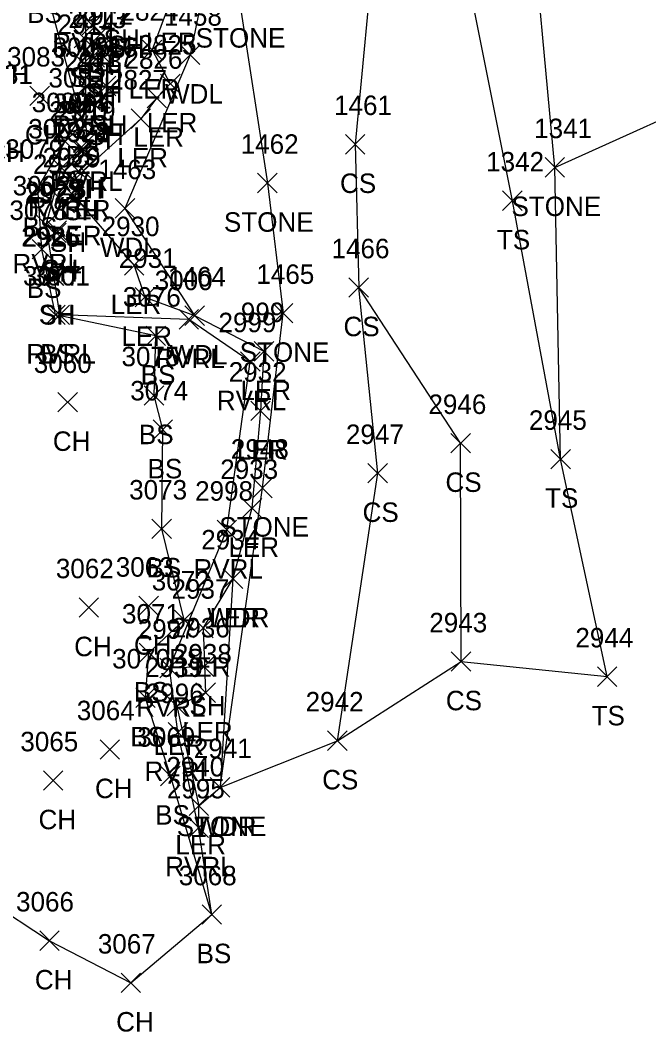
# Model space of a CAD drawing. Extents: x 1512665 to 1513714, y 110636 to 112816.
# Drawn here: x 1513100.4 to 1513164.9, y 110636.4 to 110740.2 of the extents above; entities that cross this region are included whole.
import ezdxf

# ---------------------------------------------------------------- set-up
doc = ezdxf.new("R2010")
doc.units = 0
for name, color, linetype in [('L_A', 7, 'Continuous'), ('L_I', 7, 'Continuous'), ('L_TIC', 7, 'Continuous'), ('LARO', 7, 'Continuous'), ('LASF', 7, 'Continuous'), ('LAWA', 7, 'Continuous'), ('LAWE', 7, 'Continuous'), ('LELB', 7, 'Continuous'), ('LSOGP', 7, 'Continuous')]:
    doc.layers.add(name, color=color, linetype=linetype)

msp = doc.modelspace()

# ---------------------------------------------------------------- linework, layer by layer
at = {"layer": 'L_TIC'}
for points in [[(1513106.72, 110738.74), (1513108.72, 110740.74)], [(1513108.72, 110738.74), (1513106.72, 110740.74)], [(1513107.68, 110737.88), (1513109.68, 110739.88)], [(1513109.68, 110737.88), (1513107.68, 110739.88)], [(1513105.89, 110737.4), (1513107.89, 110739.4)], [(1513107.89, 110737.4), (1513105.89, 110739.4)], [(1513107.65, 110736.34), (1513109.65, 110738.34)], [(1513109.65, 110736.34), (1513107.65, 110738.34)], [(1513107.67, 110735.77), (1513109.67, 110737.77)], [(1513109.67, 110735.77), (1513107.67, 110737.77)], [(1513112.92, 110736.19), (1513114.92, 110738.19)], [(1513114.92, 110736.19), (1513112.92, 110738.19)], [(1513116.81, 110735.67), (1513118.81, 110737.67)], [(1513118.81, 110735.67), (1513116.81, 110737.67)], [(1513105.87, 110734.82), (1513107.87, 110736.82)], [(1513107.87, 110734.82), (1513105.87, 110736.82)], [(1513107, 110735.42), (1513109, 110737.42)], [(1513109, 110735.42), (1513107, 110737.42)], [(1513106.11, 110732.46), (1513108.11, 110734.46)], [(1513108.11, 110732.46), (1513106.11, 110734.46)], [(1513108.18, 110732.48), (1513110.18, 110734.48)], [(1513110.18, 110732.48), (1513108.18, 110734.48)], [(1513114.77, 110732.71), (1513116.77, 110734.71)], [(1513116.77, 110732.71), (1513114.77, 110734.71)], [(1513101.35, 110731.48), (1513103.35, 110733.48)], [(1513103.35, 110731.48), (1513101.35, 110733.48)], [(1513107.79, 110731.42), (1513109.79, 110733.42)], [(1513109.79, 110731.42), (1513107.79, 110733.42)], [(1513106.56, 110730.99), (1513108.56, 110732.99)], [(1513108.56, 110730.99), (1513106.56, 110732.99)], [(1513113.39, 110731.25), (1513115.39, 110733.25)], [(1513115.39, 110731.25), (1513113.39, 110733.25)], [(1513105.6, 110729.32), (1513107.6, 110731.32)], [(1513107.6, 110729.32), (1513105.6, 110731.32)], [(1513111.74, 110729.12), (1513113.74, 110731.12)], [(1513113.74, 110729.12), (1513111.74, 110731.12)], [(1513103.97, 110726.79), (1513105.97, 110728.79)], [(1513105.97, 110726.79), (1513103.97, 110728.79)], [(1513106.17, 110726.71), (1513108.17, 110728.71)], [(1513108.17, 110726.71), (1513106.17, 110728.71)], [(1513133.76, 110726.5), (1513135.76, 110728.5)], [(1513135.76, 110726.5), (1513133.76, 110728.5)], [(1513105.68, 110725.91), (1513107.68, 110727.91)], [(1513107.68, 110725.91), (1513105.68, 110727.91)], [(1513105.9, 110725.94), (1513107.9, 110727.94)], [(1513107.9, 110725.94), (1513105.9, 110727.94)], [(1513103.59, 110724.09), (1513105.59, 110726.09)], [(1513105.59, 110724.09), (1513103.59, 110726.09)], [(1513105.4, 110723.7), (1513107.4, 110725.7)], [(1513107.4, 110723.7), (1513105.4, 110725.7)], [(1513105.85, 110723.79), (1513107.85, 110725.79)], [(1513107.85, 110723.79), (1513105.85, 110725.79)], [(1513154.27, 110724.13), (1513156.27, 110726.13)], [(1513156.27, 110724.13), (1513154.27, 110726.13)], [(1513124.74, 110722.52), (1513126.74, 110724.52)], [(1513126.74, 110722.52), (1513124.74, 110724.52)], [(1513101.16, 110722.01), (1513103.16, 110724.01)], [(1513103.16, 110722.01), (1513101.16, 110724.01)], [(1513104.93, 110721.13), (1513106.93, 110723.13)], [(1513106.93, 110721.13), (1513104.93, 110723.13)], [(1513103.93, 110720.46), (1513105.93, 110722.46)], [(1513105.93, 110720.46), (1513103.93, 110722.46)], [(1513149.9, 110720.71), (1513151.9, 110722.71)], [(1513151.9, 110720.71), (1513149.9, 110722.71)], [(1513110.12, 110719.92), (1513112.12, 110721.92)], [(1513112.12, 110719.92), (1513110.12, 110721.92)], [(1513102.01, 110718.25), (1513104.01, 110720.25)], [(1513104.01, 110718.25), (1513102.01, 110720.25)], [(1513103.08, 110717.41), (1513105.08, 110719.41)], [(1513105.08, 110717.41), (1513103.08, 110719.41)], [(1513103.12, 110717.65), (1513105.12, 110719.65)], [(1513105.12, 110717.65), (1513103.12, 110719.65)], [(1513101.58, 110715.73), (1513103.58, 110717.73)], [(1513103.58, 110715.73), (1513101.58, 110717.73)], [(1513111.07, 110714.07), (1513113.07, 110716.07)], [(1513113.07, 110714.07), (1513111.07, 110716.07)], [(1513102.77, 110713.03), (1513104.77, 110715.03)], [(1513104.77, 110713.03), (1513102.77, 110715.03)], [(1513102.84, 110712.99), (1513104.84, 110714.99)], [(1513104.84, 110712.99), (1513102.84, 110714.99)], [(1513134.12, 110711.8), (1513136.12, 110713.8)], [(1513136.12, 110711.8), (1513134.12, 110713.8)], [(1513112.17, 110710.81), (1513114.17, 110712.81)], [(1513114.17, 110710.81), (1513112.17, 110712.81)], [(1513102.98, 110708.99), (1513104.98, 110710.99)], [(1513104.98, 110708.99), (1513102.98, 110710.99)], [(1513103.42, 110709), (1513105.42, 110711)], [(1513105.42, 110709), (1513103.42, 110711)], [(1513117.27, 110708.91), (1513119.27, 110710.91)], [(1513119.27, 110708.91), (1513117.27, 110710.91)], [(1513126.35, 110709.17), (1513128.35, 110711.17)], [(1513128.35, 110709.17), (1513126.35, 110711.17)], [(1513116.67, 110708.53), (1513118.67, 110710.53)], [(1513118.67, 110708.53), (1513116.67, 110710.53)], [(1513113.29, 110706.84), (1513115.29, 110708.84)], [(1513115.29, 110706.84), (1513113.29, 110708.84)], [(1513124.39, 110705.25), (1513126.39, 110707.25)], [(1513126.39, 110705.25), (1513124.39, 110707.25)], [(1513122.99, 110704.21), (1513124.99, 110706.21)], [(1513124.99, 110704.21), (1513122.99, 110706.21)], [(1513113.1, 110700.72), (1513115.1, 110702.72)], [(1513115.1, 110700.72), (1513113.1, 110702.72)], [(1513104.23, 110700.03), (1513106.23, 110702.03)], [(1513106.23, 110700.03), (1513104.23, 110702.03)], [(1513124.03, 110699.14), (1513126.03, 110701.14)], [(1513126.03, 110699.14), (1513124.03, 110701.14)], [(1513114, 110697.21), (1513116, 110699.21)], [(1513116, 110697.21), (1513114, 110699.21)], [(1513144.59, 110695.82), (1513146.59, 110697.82)], [(1513146.59, 110695.82), (1513144.59, 110697.82)], [(1513154.86, 110694.19), (1513156.86, 110696.19)], [(1513156.86, 110694.19), (1513154.86, 110696.19)], [(1513136.07, 110692.74), (1513138.07, 110694.74)], [(1513138.07, 110692.74), (1513136.07, 110694.74)], [(1513124.25, 110691.23), (1513126.25, 110693.23)], [(1513126.25, 110691.23), (1513124.25, 110693.23)], [(1513123.16, 110689.15), (1513125.16, 110691.15)], [(1513125.16, 110689.15), (1513123.16, 110691.15)], [(1513113.89, 110687.04), (1513115.89, 110689.04)], [(1513115.89, 110687.04), (1513113.89, 110689.04)], [(1513120.58, 110686.92), (1513122.58, 110688.92)], [(1513122.58, 110686.92), (1513120.58, 110688.92)], [(1513121.21, 110681.92), (1513123.21, 110683.92)], [(1513123.21, 110681.92), (1513121.21, 110683.92)], [(1513121.21, 110681.92), (1513123.21, 110683.92)], [(1513123.21, 110681.92), (1513121.21, 110683.92)], [(1513106.41, 110678.96), (1513108.41, 110680.96)], [(1513108.41, 110678.96), (1513106.41, 110680.96)], [(1513112.55, 110679.12), (1513114.55, 110681.12)], [(1513114.55, 110679.12), (1513112.55, 110681.12)], [(1513116.2, 110677.7), (1513118.2, 110679.7)], [(1513118.2, 110677.7), (1513116.2, 110679.7)], [(1513118.16, 110676.86), (1513120.16, 110678.86)], [(1513120.16, 110676.86), (1513118.16, 110678.86)], [(1513112.58, 110674.31), (1513114.58, 110676.31)], [(1513114.58, 110674.31), (1513112.58, 110676.31)], [(1513144.63, 110673.41), (1513146.63, 110675.41)], [(1513146.63, 110673.41), (1513144.63, 110675.41)], [(1513114.69, 110672.75), (1513116.69, 110674.75)], [(1513116.69, 110672.75), (1513114.69, 110674.75)], [(1513118.24, 110672.89), (1513120.24, 110674.89)], [(1513120.24, 110672.89), (1513118.24, 110674.89)], [(1513159.63, 110671.86), (1513161.63, 110673.86)], [(1513161.63, 110671.86), (1513159.63, 110673.86)], [(1513118.4, 110670.21), (1513120.4, 110672.21)], [(1513120.4, 110670.21), (1513118.4, 110672.21)], [(1513112.23, 110669.7), (1513114.23, 110671.7)], [(1513114.23, 110669.7), (1513112.23, 110671.7)], [(1513115.45, 110668.83), (1513117.45, 110670.83)], [(1513117.45, 110668.83), (1513115.45, 110670.83)], [(1513115.56, 110666.15), (1513117.56, 110668.15)], [(1513117.56, 110666.15), (1513115.56, 110668.15)], [(1513131.93, 110665.29), (1513133.93, 110667.29)], [(1513133.93, 110665.29), (1513131.93, 110667.29)], [(1513108.56, 110664.39), (1513110.56, 110666.39)], [(1513110.56, 110664.39), (1513108.56, 110666.39)], [(1513102.75, 110661.2), (1513104.75, 110663.2)], [(1513104.75, 110661.2), (1513102.75, 110663.2)], [(1513114.78, 110661.67), (1513116.78, 110663.67)], [(1513116.78, 110661.67), (1513114.78, 110663.67)], [(1513119.88, 110660.5), (1513121.88, 110662.5)], [(1513121.88, 110660.5), (1513119.88, 110662.5)], [(1513119.88, 110660.5), (1513121.88, 110662.5)], [(1513121.88, 110660.5), (1513119.88, 110662.5)], [(1513117.71, 110658.62), (1513119.71, 110660.62)], [(1513119.71, 110658.62), (1513117.71, 110660.62)], [(1513117.68, 110656.37), (1513119.68, 110658.37)], [(1513119.68, 110656.37), (1513117.68, 110658.37)], [(1513119.03, 110647.45), (1513121.03, 110649.45)], [(1513121.03, 110647.45), (1513119.03, 110649.45)], [(1513102.37, 110644.76), (1513104.37, 110646.76)], [(1513104.37, 110644.76), (1513102.37, 110646.76)], [(1513110.72, 110640.44), (1513112.72, 110642.44)], [(1513112.72, 110640.44), (1513110.72, 110642.44)]]:
    msp.add_lwpolyline(points, dxfattribs=at)
at = {"layer": 'LARO'}
for points in [[(1513106.91, 110772.08), (1513107.31, 110766.04), (1513109.04, 110753.4), (1513118.93, 110746.43), (1513115.69, 110741.97), (1513113.92, 110737.19), (1513115.77, 110733.71), (1513114.39, 110732.25), (1513112.74, 110730.12), (1513106.85, 110724.79), (1513105.93, 110722.13), (1513112.07, 110715.07), (1513113.17, 110711.81)], [(1513113.17, 110711.81), (1513118.27, 110709.91)], [(1513125.39, 110706.25), (1513125.03, 110700.14), (1513124.16, 110690.15), (1513122.21, 110682.92), (1513119.16, 110677.86), (1513119.4, 110671.21), (1513116.45, 110669.83), (1513118.71, 110659.62)]]:
    msp.add_lwpolyline(points, dxfattribs=at)
at = {"layer": 'LASF'}
for points in [[(1513155.27, 110725.13), (1513152.55, 110754.36), (1513148, 110771.81), (1513152.25, 110792.5), (1513164.38, 110807.2), (1513174.01, 110832.48), (1513163.39, 110825.71), (1513157.64, 110817.68), (1513150.03, 110815.28), (1513143.72, 110818.88), (1513137.14, 110819.49), (1513132.38, 110806.57), (1513129.37, 110796.51), (1513123.12, 110784.14), (1513118.15, 110774.69), (1513122.72, 110764.73), (1513123.65, 110752.31), (1513122.83, 110742.42), (1513125.74, 110723.52), (1513127.35, 110710.17)], [(1513125.25, 110692.23), (1513127.35, 110710.17)], [(1513120.88, 110661.5), (1513125.25, 110692.23)]]:
    msp.add_lwpolyline(points, dxfattribs=at)
at = {"layer": 'LAWA'}
for points in [[(1513169.91, 110850.57), (1513155.8, 110854.74), (1513154, 110850), (1513151.76, 110839.77), (1513151, 110833.43), (1513152.45, 110822.76), (1513150.03, 110815.28), (1513136.76, 110804.59), (1513129.37, 110796.51), (1513125.79, 110797.84), (1513115.01, 110789.72), (1513110.23, 110788.6), (1513101.86, 110785.92), (1513106.09, 110777.42), (1513109.38, 110771.51), (1513113.64, 110761.19), (1513120.12, 110747.9), (1513117.81, 110736.67), (1513111.12, 110720.92), (1513118.27, 110709.91)], [(1513118.27, 110709.91), (1513125.39, 110706.25)], [(1513122.21, 110682.92), (1513120.88, 110661.5)]]:
    msp.add_lwpolyline(points, dxfattribs=at)
at = {"layer": 'LAWE'}
for points in [[(1513118.68, 110657.37), (1513116.56, 110667.15), (1513115.69, 110673.75), (1513121.58, 110687.92), (1513123.99, 110705.21), (1513117.67, 110709.53), (1513104.42, 110710), (1513103.01, 110719.25), (1513104.59, 110725.09), (1513107.17, 110727.71), (1513107.11, 110733.46), (1513107.09, 110741.93), (1513105.6, 110746.77), (1513105.66, 110753.5), (1513104.91, 110762.33), (1513105.87, 110773.95), (1513104.64, 110776.81), (1513101.3, 110781.34), (1513097.52, 110782.31), (1513095.21, 110782.03), (1513085.65, 110788.4)], [(1513115.69, 110673.75), (1513119.24, 110673.89)]]:
    msp.add_lwpolyline(points, dxfattribs=at)
at = {"layer": 'LELB'}
for points in [[(1513143.72, 110818.88), (1513136.76, 110804.59), (1513128.22, 110782.29), (1513129.05, 110765.49), (1513132.8, 110753.07), (1513136.85, 110749.57), (1513134.76, 110727.5), (1513135.12, 110712.8)], [(1513120.03, 110648.45), (1513115.78, 110662.67), (1513113.23, 110670.7), (1513113.58, 110675.31), (1513117.2, 110678.7), (1513114.89, 110688.04), (1513115, 110698.21), (1513114.1, 110701.72), (1513114.29, 110707.84), (1513103.98, 110709.99), (1513102.58, 110716.73), (1513102.16, 110723.01), (1513104.97, 110727.79), (1513106.6, 110730.32), (1513102.63, 110744.95), (1513102.62, 110755.29), (1513102.67, 110763.59), (1513103.29, 110769.92), (1513102.85, 110777.18), (1513094.79, 110781.14), (1513084.1, 110788.5)], [(1513150.9, 110721.71), (1513145.27, 110749.95), (1513148, 110771.81)], [(1513155.86, 110695.19), (1513150.9, 110721.71)], [(1513145.59, 110696.82), (1513135.12, 110712.8)], [(1513137.07, 110693.74), (1513135.12, 110712.8)], [(1513145.63, 110674.41), (1513145.59, 110696.82)], [(1513160.63, 110672.86), (1513155.86, 110695.19)], [(1513132.93, 110666.29), (1513137.07, 110693.74)]]:
    msp.add_lwpolyline(points, dxfattribs=at)
at = {"layer": 'LSOGP'}
msp.add_lwpolyline([(1512993.75, 110649.55), (1513006.94, 110650.52), (1513019.77, 110651.83), (1513045.3, 110650.29), (1513048.61, 110650.08), (1513058.22, 110648.71), (1513066.99, 110648.2), (1513071.29, 110647.63), (1513083.45, 110649.3), (1513097.01, 110649.92), (1513103.37, 110645.76), (1513111.72, 110641.44), (1513120.03, 110648.44), (1513118.68, 110657.37), (1513118.71, 110659.62), (1513120.88, 110661.5), (1513132.93, 110666.29), (1513145.63, 110674.41), (1513160.63, 110672.86), (1513155.86, 110695.19), (1513155.27, 110725.13), (1513174.53, 110733.79)], dxfattribs=at)

# ---------------------------------------------------------------- texts
at = {"layer": 'L_A'}
for s, p in [('BS', (1513101.07, 110739.95)), ('RVRL', (1513103.66, 110736.93)), ('SH', (1513108.93, 110737.28)), ('SH', (1513109.41, 110736.64)), ('LER', (1513113.27, 110736.97)), ('STONE', (1513118.38, 110737.42)), ('SH', (1513109.4, 110736.35)), ('SH', (1513106.21, 110734.74)), ('CH', (1513097.38, 110733.67)), ('SH', (1513107.17, 110733.88)), ('SH', (1513105.38, 110733.4)), ('SH', (1513106.49, 110731.42)), ('SH', (1513107.14, 110732.34)), ('SH', (1513107.16, 110731.77)), ('LER', (1513111.5, 110732.19)), ('WDL', (1513115.23, 110731.67)), ('SH', (1513105.36, 110730.82)), ('RVRL', (1513103.67, 110728.46)), ('SH', (1513107.67, 110728.48)), ('LER', (1513113.35, 110728.71)), ('CH', (1513100.84, 110727.48)), ('SH', (1513107.28, 110727.42)), ('SH', (1513106.04, 110726.99)), ('LER', (1513111.97, 110727.25)), ('CH', (1513096.97, 110725.68)), ('BS', (1513105.04, 110725.32)), ('LER', (1513110.33, 110725.12)), ('BS', (1513103.41, 110722.79)), ('RVRL', (1513103.74, 110722.71)), ('CS', (1513133.2, 110722.5)), ('SH', (1513105.17, 110721.91)), ('SH', (1513105.39, 110721.94)), ('RVRL', (1513101.16, 110720.09)), ('STONE', (1513150.81, 110720.13)), ('LER', (1513104.43, 110719.79)), ('SH', (1513104.88, 110719.7)), ('BS', (1513100.6, 110718.01)), ('STONE', (1513121.28, 110718.52)), ('LER', (1513103.51, 110717.13)), ('SH', (1513103.41, 110716.46)), ('WDL', (1513108.54, 110715.92)), ('TS', (1513149.31, 110716.71)), ('RVRL', (1513099.57, 110714.25)), ('SH', (1513102.57, 110713.41)), ('SH', (1513102.61, 110713.65)), ('BS', (1513101.03, 110711.73)), ('LER', (1513109.65, 110710.07)), ('SH', (1513102.26, 110709.03)), ('SH', (1513102.33, 110708.99)), ('CS', (1513133.56, 110707.8)), ('LER', (1513110.75, 110706.81)), ('RVRL', (1513100.99, 110705)), ('BS', (1513102.42, 110704.99)), ('RVRL', (1513114.24, 110704.53)), ('WDL', (1513115.69, 110704.91)), ('STONE', (1513122.9, 110705.17)), ('BS', (1513112.73, 110702.84)), ('LER', (1513122.97, 110701.25)), ('RVRL', (1513120.55, 110700.21)), ('BS', (1513112.54, 110696.72)), ('CH', (1513103.71, 110696.03)), ('LER', (1513122.61, 110695.14)), ('BS', (1513113.44, 110693.21)), ('CS', (1513144.03, 110691.82)), ('TS', (1513154.26, 110690.19)), ('CS', (1513135.52, 110688.74)), ('STONE', (1513120.8, 110687.23)), ('LER', (1513121.74, 110685.15)), ('BS', (1513113.33, 110683.04)), ('RVRL', (1513118.15, 110682.92)), ('WDR', (1513119.57, 110677.92)), ('LER', (1513119.79, 110677.92)), ('CH', (1513105.9, 110674.96)), ('CH', (1513112.04, 110675.12)), ('BS', (1513115.65, 110673.7)), ('LER', (1513116.75, 110672.86)), ('BS', (1513112.02, 110670.31)), ('CS', (1513144.07, 110669.41)), ('RVRL', (1513112.26, 110668.75)), ('SH', (1513117.73, 110668.89)), ('TS', (1513159.04, 110667.86)), ('LER', (1513116.98, 110666.21)), ('BS', (1513111.67, 110665.7)), ('LER', (1513114.04, 110664.83)), ('RVRL', (1513113.13, 110662.15)), ('CS', (1513131.37, 110661.29)), ('CH', (1513108.04, 110660.39)), ('CH', (1513102.24, 110657.2)), ('BS', (1513114.22, 110657.67)), ('STONE', (1513116.43, 110656.5)), ('WDR', (1513118.24, 110656.5)), ('LER', (1513116.29, 110654.62)), ('RVRL', (1513115.25, 110652.37)), ('BS', (1513118.47, 110643.45)), ('CH', (1513101.86, 110640.76)), ('CH', (1513110.21, 110636.44))]:
    msp.add_text(s, height=2, dxfattribs=at).set_placement(p)
at = {"layer": 'L_I'}
for s, p in [('2912', (1513105.98, 110739.77)), ('2824', (1513110.66, 110740.19)), ('2914', (1513104.18, 110738.82)), ('2913', (1513105.31, 110739.42)), ('1458', (1513115.12, 110739.67)), ('2825', (1513112.51, 110736.71)), ('3005', (1513103.69, 110736.46)), ('2916', (1513106.43, 110736.48)), ('3083', (1513099.01, 110735.48)), ('2918', (1513104.86, 110734.99)), ('2917', (1513106.1, 110735.42)), ('2826', (1513111.07, 110735.25)), ('3081', (1513095.71, 110733.68)), ('3082', (1513103.26, 110733.32)), ('2827', (1513109.48, 110733.12)), ('3080', (1513101.54, 110730.79)), ('3004', (1513103.76, 110730.71)), ('1461', (1513132.59, 110730.5)), ('2920', (1513103.33, 110729.91)), ('2919', (1513104.2, 110729.94)), ('3003', (1513101.18, 110728.09)), ('2828', (1513103.59, 110727.79)), ('2921', (1513103.7, 110727.7)), ('1341', (1513153.14, 110728.13)), ('1462', (1513123, 110726.52)), ('3079', (1513098.82, 110726.01)), ('2922', (1513101.67, 110724.46)), ('2929', (1513102.66, 110725.13)), ('1342', (1513148.21, 110724.71)), ('1463', (1513108.38, 110723.92)), ('3002', (1513099.59, 110722.25)), ('2924', (1513100.82, 110721.41)), ('2923', (1513100.86, 110721.65)), ('3078', (1513099.25, 110719.73)), ('2930', (1513108.72, 110718.07)), ('2926', (1513100.46, 110717.03)), ('2925', (1513100.58, 110716.99)), ('2931', (1513110.48, 110714.81)), ('1466', (1513132.33, 110715.8)), ('3077', (1513100.64, 110712.99)), ('3001', (1513101.57, 110713)), ('1464', (1513115.53, 110712.91)), ('1465', (1513124.61, 110713.17)), ('3000', (1513114.17, 110712.53)), ('3076', (1513110.9, 110710.84)), ('999', (1513123.02, 110709.25)), ('2999', (1513120.72, 110708.21)), ('3075', (1513110.76, 110704.72)), ('3060', (1513101.75, 110704.03)), ('2932', (1513121.77, 110703.14)), ('3074', (1513111.66, 110701.21)), ('2946', (1513142.28, 110699.82)), ('2945', (1513152.6, 110698.19)), ('2947', (1513133.81, 110696.74)), ('2948', (1513121.99, 110695.23)), ('2933', (1513120.9, 110693.15)), ('3073', (1513111.55, 110691.04)), ('2998', (1513118.32, 110690.92)), ('2934', (1513118.95, 110685.92)), ('2934', (1513118.95, 110685.92)), ('3062', (1513104.02, 110682.96)), ('3063', (1513110.17, 110683.12)), ('3072', (1513113.87, 110681.7)), ('2937', (1513115.9, 110680.86)), ('3071', (1513110.81, 110678.31)), ('2943', (1513142.37, 110677.41)), ('2997', (1513112.43, 110676.75)), ('2936', (1513115.93, 110676.89)), ('2944', (1513157.37, 110675.86)), ('3070', (1513109.8, 110673.7)), ('2938', (1513116.14, 110674.21)), ('2939', (1513113.18, 110672.83)), ('2996', (1513113.25, 110670.15)), ('2942', (1513129.67, 110669.29)), ('3064', (1513106.17, 110668.39)), ('3065', (1513100.37, 110665.2)), ('3069', (1513112.39, 110665.67)), ('2941', (1513118.19, 110664.5)), ('2941', (1513118.19, 110664.5)), ('2940', (1513115.36, 110662.62)), ('2995', (1513115.42, 110660.37)), ('3068', (1513116.64, 110651.45)), ('3066', (1513099.93, 110648.76)), ('3067', (1513108.33, 110644.44))]:
    msp.add_text(s, height=2, dxfattribs=at).set_placement(p)

doc.saveas('drawing.dxf')
